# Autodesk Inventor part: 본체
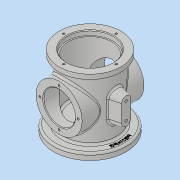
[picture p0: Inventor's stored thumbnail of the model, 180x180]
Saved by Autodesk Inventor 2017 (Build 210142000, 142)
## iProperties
Part Number: 본체
Material: 일반
Document SubType Name: Modeling
Designer: MRC
Density: 1 g/cm^3
Appearance: 기본값
Mass: 293.451 g
Surface Area: 769.493 cm^2
Volume: 293.451 cm^3
Author: MRC
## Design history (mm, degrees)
sketch "스케치1"
  geometry: C1 r 55 at (0, 0); 1 further point
  constraints: 1 centre point, 1 coincident
  dimensions: "d0" = 110 diameter of C1
extrude "돌출1" new body sketch "스케치1" distance "d1" = 10; taper "d2" = 0 deg
sketch "스케치2"
  geometry: C1 r 40 at (0, 0); 1 further point
  constraints: 1 centre point, 1 coincident
  dimensions: "d3" = 80 diameter of C1
extrude "돌출2" join sketch "스케치2" distance "d4" = 88; taper "d5" = 0 deg
sketch "스케치3"
  geometry: C1 r 47 at (0, 0); 1 further point
  constraints: 1 centre point, 1 coincident
  dimensions: "d6" = 94 diameter of C1
extrude "돌출3" join sketch "스케치3" distance "d7" = 10; taper "d8" = 0 deg
sketch "스케치4"
  geometry: L1 (-55, 0)-(55, 0) reference; C1 r 35 at (0, 54); 1 further point
  constraints: 1 centre point, 1 vertical alignment
  dimensions: "d9" = 70 diameter of C1; "d10" = 54 distance from line of L1 C1.centre
extrude "돌출4" join sketch "스케치4" stored distance "d11" = 94; taper "d12" = 0 deg
sketch "스케치5"
  geometry: C1 r 35 at (0, 0); 1 further point
  constraints: 1 centre point, 1 coincident
  dimensions: "d13" = 70 diameter of C1
extrude "돌출5" cut sketch "스케치5" distance "d14" = 7; taper "d15" = 0 deg
sketch "스케치6"
  geometry: C1 r 33 at (0, 0); 1 further point
  constraints: 1 centre point, 1 coincident
  dimensions: "d16" = 66 diameter of C1
extrude "돌출6" cut sketch "스케치6" distance "d17" = 79; taper "d18" = 0 deg
sketch "스케치7"
  geometry: C1 r 33 at (0, 0); 1 further point
  constraints: 1 centre point, 1 coincident
  dimensions: "d19" = 66 diameter of C1
extrude "돌출7" cut sketch "스케치7" distance "d20" = 16; taper "d21" = 0 deg
sketch "스케치8"
  geometry: C1 r 5 at (0, 0); 1 further point
  constraints: 1 centre point, 1 coincident
  dimensions: "d22" = 10 diameter of C1
extrude "돌출8" cut sketch "스케치8" distance "d23" = 16; taper "d24" = 0 deg
sketch "스케치9"
  geometry: C1 r 24 at (0, 0); 2 further points
  constraints: 1 centre point, 1 horizontal alignment, 1 vertical alignment, 1 other
  dimensions: "d25" = 48 diameter of C1
extrude "돌출9" cut sketch "스케치9" distance "d26" = 94; taper "d27" = 0 deg
sketch "스케치10"
  geometry: C1 r 24 at (0, 0) reference; C2 r 35 at (0, 0) reference; A1 r 29 centre (0, 0) between (0, 29) and (-29, 0); 3 further points
  constraints: 4 point on circle, 2 horizontal alignment, 2 vertical alignment, 1 centre point, 1 coincident
  dimensions: "d28" = 58 diameter of A1
hole "구멍1" sketch "스케치10" at (0, 29), (-29, 0), (29, 0), (0, -29) diameter "d29" = 3.242; stored, may be unused: countersink angle "d33" = 90 deg, drill point angle "d35" = 118 deg; dims "d30" = 6, "d31" = 4, "d32" = 2, "d34" = 8
sketch "스케치11"
  geometry: C1 r 35 at (0, 0) reference; C2 r 47 at (0, 0) reference; A1 r 40 centre (0, 0) between (0, 40) and (-40, 0); 3 further points
  constraints: 4 point on circle, 2 horizontal alignment, 2 vertical alignment, 1 centre point, 1 coincident
  dimensions: "d36" = 80 diameter of A1
hole "구멍2" sketch "스케치11" at (0, 40), (-40, 0), (0, -40), (40, 0) diameter "d37" = 3.242; stored, may be unused: countersink angle "d41" = 90 deg, drill point angle "d43" = 118 deg; dims "d38" = 6, "d39" = 4, "d40" = 2, "d42" = 8
node "작업 평면1"
sketch "스케치12"
  geometry: L1 (67, 0)-(41, 0); L2 (67, 7)-(41, 7); L3 (41, -7)-(67, -7); L4 (0, 55)-(0, -55) reference; A1 r 7 centre (67, 0) between (67, -7) and (67, 7); A2 r 7 centre (41, 0) between (41, 7) and (41, -7); 3 further points
  constraints: 8 end point, 4 point on circle, 4 tangent, 2 centre point, 2 midpoint, 1 horizontal, 1 horizontal alignment, 1 parallel
  dimensions: "d46" = 7 radius of A1; "d47" = 54 distance from line of point (54, 0) L4; "d50" = 40 dimension on A2 A1
extrude "돌출10" join sketch "스케치12" stored distance "d48" = 94; taper "d49" = 15 deg
sketch "스케치14"
  geometry: L1 (-7, 67)-(-7, 41) reference; L2 (7, 41)-(7, 67) reference; A1 r 7 centre (0, 41) between (-7, 41) and (7, 41) reference; A2 r 7 centre (0, 67) between (7, 67) and (-7, 67) reference; 3 further points
  constraints: 2 coincident
hole "구멍3" sketch "스케치14" at (0, 67), (0, 41) diameter "d51" = 4.134; stored, may be unused: countersink angle "d55" = 90 deg, drill point angle "d57" = 118 deg; dims "d52" = 6, "d53" = 4, "d54" = 2, "d56" = 8
chamfer "모따기1" distance "d58" = 1; stored, may be unused: second distance "d59" = 2, angle "d60" = 45 deg
fillet "모깎기1" dims "d61" = 3
fillet "모깎기2" dims "d62" = 3
sketch "스케치15"
  geometry: C1 r 50 at (0, 0); 1 further point
  constraints: 1 centre point, 1 coincident, 1 other
  dimensions: "d63" = 100 diameter of C1
feature "엠보싱1" sketch "스케치15" dims "d64" = 0.5, "d65" = 0
node "솔리드1"
mirror "미러1"
node "투영된 루프1"
node "투영된 루프2"
node "투영된 루프3"
other parameters: "d44" = 55
